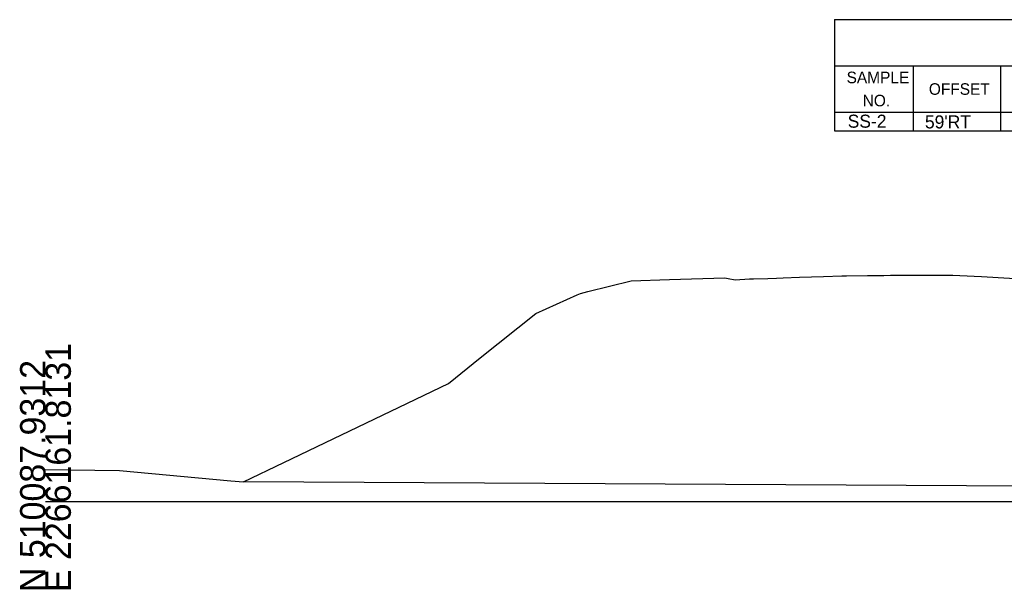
# Model space of a CAD drawing. Extents: x -827 to 2303, y -169 to 9934.
# Drawn here: x -2.8 to 105.7, y 6990.3 to 7053.1 of the extents above; entities that cross this region are included whole.
import ezdxf

# ---------------------------------------------------------------- set-up
doc = ezdxf.new("R2010")
doc.units = 0
for name, color, linetype in [('Default', 7, 'Continuous'), ('Exist Cross Section Cell', 7, 'Continuous'), ('Exist XS Ground Line', 7, 'Continuous'), ('Geotech Sheets and Borders Cell', 7, 'Continuous'), ('Prop DirtTable_ Soil Test Results - Tx (Sample Data)', 7, 'Continuous'), ('Prop Road Sect_ Material - Contact (General - Major)', 7, 'Continuous')]:
    doc.layers.add(name, color=color, linetype=linetype)

msp = doc.modelspace()

# ---------------------------------------------------------------- linework, layer by layer
at = {"layer": 'Exist Cross Section Cell'}
msp.add_line((0, 7000), (150, 7000), dxfattribs=at)
at = {"layer": 'Exist XS Ground Line'}
msp.add_lwpolyline([(0, 7003.53), (8.16, 7003.42), (20.43, 7002.28), (21.83, 7002.15), (26.27, 7004.28), (44.46, 7013), (47.94, 7015.83), (54.09, 7020.75), (58.62, 7022.78), (58.99, 7022.95), (59.83, 7023.15), (64.61, 7024.34), (68.81, 7024.48), (74.92, 7024.68), (75.28, 7024.61), (76.05, 7024.45), (77.64, 7024.55), (78.09, 7024.55), (79.66, 7024.61), (80.62, 7024.64), (81.37, 7024.67), (83.15, 7024.74), (85.82, 7024.8), (87.83, 7024.89), (88.33, 7024.89), (90.67, 7024.91), (92.47, 7024.94), (93.18, 7024.95), (94.1, 7024.95), (95.71, 7024.95), (97, 7024.97), (98.23, 7024.98), (98.76, 7024.98), (100.08, 7024.98), (100.85, 7024.94), (103.21, 7024.8), (110.03, 7024.4)], dxfattribs=at)
at = {"layer": 'Geotech Sheets and Borders Cell'}
for p, q in [((87.02, 7053.15), (87.02, 7042.95)), ((87.02, 7053.15), (214.82, 7053.15)), ((87.02, 7048.05), (214.82, 7048.05)), ((95.7, 7048.05), (95.7, 7040.89)), ((105.31, 7048.05), (105.31, 7040.89)), ((87.02, 7042.95), (214.82, 7042.95)), ((87.02, 7042.95), (214.82, 7042.95)), ((87.02, 7042.95), (87.02, 7040.89)), ((87.02, 7040.89), (214.82, 7040.89)), ((87.02, 7040.89), (214.82, 7040.89))]:
    msp.add_line(p, q, dxfattribs=at)
at = {"layer": 'Prop Road Sect_ Material - Contact (General - Major)'}
msp.add_line((204.67, 7001.19), (21.83, 7002.15), dxfattribs=at)

# ---------------------------------------------------------------- texts
at = {"layer": 'Default'}
msp.add_text('-', height=0.0001, dxfattribs=at).set_placement((0, 7000))
msp.add_text('-', height=0.0001, dxfattribs=at).set_placement((0, 7000))
at = {"layer": 'Exist Cross Section Cell'}
for s, p in [('E 2266161.8131', (2.8, 6990)), ('N 510087.9312', (0, 6990))]:
    msp.add_text(s, height=2.8, rotation=90, dxfattribs=at).set_placement(p)
at = {"layer": 'Geotech Sheets and Borders Cell'}
for s, p in [('SAMPLE', (88.35, 7046.14)), ('OFFSET', (97.42, 7044.86)), ('NO.', (90.12, 7043.59))]:
    msp.add_text(s, height=1.275, dxfattribs=at).set_placement(p)
at = {"layer": 'Prop DirtTable_ Soil Test Results - Tx (Sample Data)'}
for s, p in [('SS-2', (88.47, 7041.23)), ("59'RT", (96.99, 7041.15))]:
    msp.add_text(s, height=1.44, dxfattribs=at).set_placement(p)

doc.saveas('drawing.dxf')
